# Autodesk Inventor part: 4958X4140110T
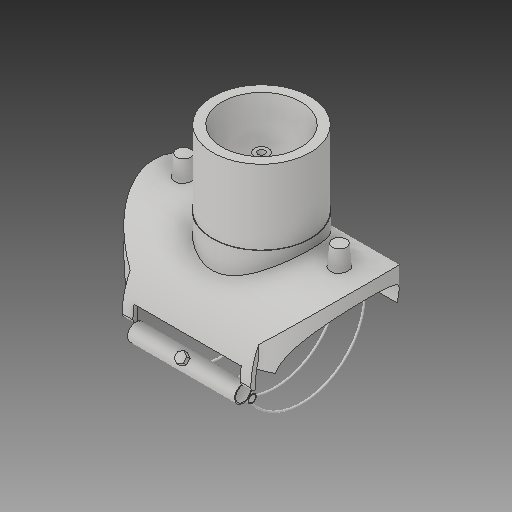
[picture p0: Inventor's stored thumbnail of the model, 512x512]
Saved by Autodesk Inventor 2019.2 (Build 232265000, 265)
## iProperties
Created: 2020-06
Part Number: 4958X4140110T
Material: Generic
Description: Plasson Branch Saddle 140x110
Document SubType Name: Modeling
Designer: KIM
Density: 1 g/cm^3
Appearance: Default
Author: KIM
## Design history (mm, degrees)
derived "4958X4.ipt"
feature "Solid1::4958X4.ipt"
tag "TaggingFeature1"
body "Solid1"
other parameters: "d0" = 242, "d3" = 169.4, "d4" = 109, "d7" = 89, "d9" = 84, "d10" = 0.5, "d11" = 1, "d12" = 27.25, "d13" = 16, "d14" = 8, "d16" = 10 deg, "d17" = 10 deg, "d19" = 0, "d23" = 0, "d26" = 0, "d27" = 145.2, "d28" = 0, "d29" = 121, "d30" = 0, "d31" = 1, "d32" = 1, "d33" = 19.2, "d34" = 9.6, "d35" = 45 deg, "d36" = 121, "d37" = 0, "d38" = 5, "d39" = 85 deg, "d40" = 27.25, "d41" = 16, "d42" = 88, "d49" = 3, "d50" = 6, "d51" = 5, "d54" = 0, "d57" = 35 deg, "d60" = 15.125, "d61" = 1, "d62" = 90 deg, "d63" = 2, "d64" = 0, "d65" = 0, "d68" = 30.25, "d70" = 0.57711, "d71" = 10 deg, "d73" = 5.145, "B" = 189, "L" = 242, "LS" = 84, "H1" = 109, "Dt" = 16, "di" = 89, "d72" = 14.7
